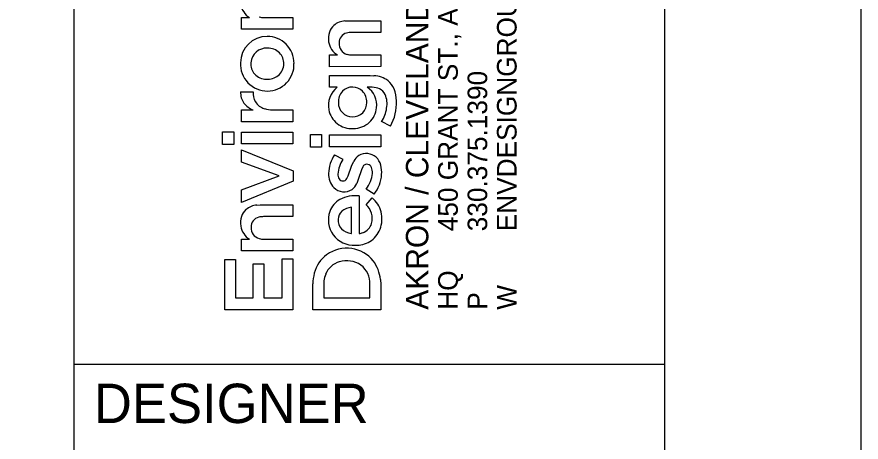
# Model space of a CAD drawing. Extents: x -0.3 to 34, y 0 to 22.
# Drawn here: x 31.854 to 34, y 2.302 to 3.382 of the extents above; entities that cross this region are included whole.
import ezdxf

# ---------------------------------------------------------------- set-up
doc = ezdxf.new("R2010")
doc.units = 0
for name, color, linetype in [('DR_P_Staging_Area', 7, 'Continuous'), ('MT_P_Drums', 7, 'Continuous'), ('SG_P_Poles', 7, 'Continuous')]:
    doc.layers.add(name, color=color, linetype=linetype)

msp = doc.modelspace()

# ---------------------------------------------------------------- linework, layer by layer
at = {"layer": 'DR_P_Staging_Area'}
msp.add_lwpolyline([(0, 0), (34, 0), (34, 22), (0, 22)], close=True, dxfattribs=at)
at = {"layer": 'MT_P_Drums'}
for p, q in [((32, 0.5), (32, 21.5)), ((32, 2.5), (33.5, 2.5))]:
    msp.add_line(p, q, dxfattribs=at)
msp.add_lwpolyline([(1.5, 21.5), (33.5, 21.5), (33.5, 0.5), (1.5, 0.5)], close=True, dxfattribs=at)
at = {"layer": 'SG_P_Poles'}
for p, q in [((32.4254, 3.3509), (32.4254, 3.3807)), ((32.4254, 3.3807), (32.4455, 3.3807)), ((32.4822, 3.3807), (32.5557, 3.3807)), ((32.5557, 3.3807), (32.5557, 3.351)), ((32.6878, 3.3722), (32.6963, 3.3727)), ((32.6963, 3.3727), (32.7792, 3.3727)), ((32.7792, 3.3727), (32.7792, 3.3429)), ((32.5557, 3.351), (32.4254, 3.3509)), ((32.7792, 3.3429), (32.7048, 3.3428)), ((32.6489, 3.2557), (32.6489, 3.2855)), ((32.6489, 3.2855), (32.669, 3.2855)), ((32.7057, 3.2855), (32.7791, 3.2855)), ((32.7791, 3.2855), (32.7792, 3.2558)), ((32.7792, 3.2558), (32.6489, 3.2557)), ((32.6489, 3.2034), (32.6489, 3.2332)), ((32.6489, 3.2332), (32.7524, 3.2332)), ((32.7524, 3.2332), (32.7619, 3.2329)), ((32.6684, 3.2034), (32.6489, 3.2034)), ((32.7576, 3.2036), (32.7449, 3.2036)), ((32.423, 3.1919), (32.4545, 3.1919)), ((32.4254, 3.1159), (32.4254, 3.1458)), ((32.4254, 3.1458), (32.4547, 3.1458)), ((32.5041, 3.1458), (32.5557, 3.1457)), ((32.5557, 3.1457), (32.5556, 3.1159)), ((32.5556, 3.1159), (32.4254, 3.1159)), ((32.8036, 3.1049), (32.7812, 3.116)), ((32.3771, 3.0582), (32.3771, 3.0903)), ((32.3771, 3.0903), (32.4054, 3.0903)), ((32.4054, 3.0903), (32.4054, 3.0582)), ((32.4254, 3.0594), (32.4254, 3.0893)), ((32.4254, 3.0893), (32.5557, 3.0893)), ((32.5557, 3.0893), (32.5557, 3.0594)), ((32.6005, 3.0511), (32.6005, 3.0832)), ((32.6005, 3.0832), (32.6289, 3.0832)), ((32.6289, 3.0832), (32.6289, 3.0511)), ((32.6489, 3.0523), (32.6489, 3.0822)), ((32.6489, 3.0822), (32.7792, 3.0822)), ((32.7792, 3.0822), (32.7792, 3.0523)), ((32.4054, 3.0582), (32.3771, 3.0582)), ((32.5557, 3.0594), (32.4254, 3.0594)), ((32.6289, 3.0511), (32.6005, 3.0511)), ((32.7792, 3.0523), (32.6489, 3.0523)), ((32.4254, 3.0133), (32.4254, 3.0446)), ((32.4254, 3.0446), (32.5567, 2.9913)), ((32.6615, 3.0321), (32.6827, 3.0203)), ((32.5212, 2.978), (32.4254, 3.0133)), ((32.7048, 3.0026), (32.7104, 3.0153)), ((32.5567, 2.9913), (32.5567, 2.9644)), ((32.6967, 2.9787), (32.7048, 3.0026)), ((32.7298, 2.9933), (32.7221, 2.9688)), ((32.7334, 3.001), (32.7298, 2.9933)), ((32.4254, 2.9429), (32.5212, 2.978)), ((32.5567, 2.9644), (32.4254, 2.9109)), ((32.693, 2.9712), (32.6967, 2.9787)), ((32.7221, 2.9688), (32.7182, 2.9592)), ((32.4254, 2.9109), (32.4254, 2.9429)), ((32.7621, 2.9314), (32.742, 2.9447)), ((32.7245, 2.9275), (32.7246, 2.8319)), ((32.7423, 2.9046), (32.7577, 2.922)), ((32.4644, 2.904), (32.4729, 2.9044)), ((32.4729, 2.9044), (32.5557, 2.9044)), ((32.5557, 2.9044), (32.5557, 2.8746)), ((32.7049, 2.8318), (32.7049, 2.8983)), ((32.5557, 2.8746), (32.4814, 2.8746)), ((32.4254, 2.7875), (32.4254, 2.8173)), ((32.4254, 2.8173), (32.4455, 2.8173)), ((32.4822, 2.8173), (32.5557, 2.8173)), ((32.5557, 2.8173), (32.5557, 2.7876)), ((32.7036, 2.8317), (32.7049, 2.8318)), ((32.5557, 2.7876), (32.4254, 2.7875)), ((32.383, 2.6379), (32.383, 2.766)), ((32.383, 2.766), (32.4101, 2.766)), ((32.4101, 2.766), (32.4101, 2.6683)), ((32.455, 2.6683), (32.455, 2.7549)), ((32.455, 2.7549), (32.4822, 2.7549)), ((32.4822, 2.7549), (32.4822, 2.6683)), ((32.5286, 2.6683), (32.5286, 2.7672)), ((32.5286, 2.7672), (32.5557, 2.7672)), ((32.5557, 2.7672), (32.5557, 2.6379)), ((32.6064, 2.638), (32.6064, 2.704)), ((32.6347, 2.7118), (32.6341, 2.7023)), ((32.7785, 2.715), (32.7792, 2.7021)), ((32.6341, 2.7023), (32.6341, 2.6684)), ((32.7515, 2.6683), (32.7515, 2.7024)), ((32.7792, 2.7021), (32.7792, 2.638)), ((32.4101, 2.6683), (32.455, 2.6683)), ((32.4822, 2.6683), (32.5286, 2.6683)), ((32.6341, 2.6684), (32.7515, 2.6683)), ((32.5557, 2.6379), (32.383, 2.6379)), ((32.7792, 2.638), (32.6064, 2.638))]:
    msp.add_line(p, q, dxfattribs=at)
for points in [[(32.4254, 3.3509), (32.4254, 3.3807), (32.4455, 3.3807)], [(32.4822, 3.3807), (32.5557, 3.3807), (32.5557, 3.351), (32.4254, 3.3509)], [(32.6878, 3.3722), (32.6963, 3.3727), (32.7792, 3.3727), (32.7792, 3.3429), (32.7048, 3.3428)], [(32.6489, 3.2557), (32.6489, 3.2855), (32.669, 3.2855)], [(32.7057, 3.2855), (32.7791, 3.2855), (32.7792, 3.2558), (32.6489, 3.2557)], [(32.6684, 3.2034), (32.6489, 3.2034), (32.6489, 3.2332), (32.7524, 3.2332), (32.7619, 3.2329)], [(32.7576, 3.2036), (32.7449, 3.2036)], [(32.423, 3.1919), (32.4545, 3.1919)], [(32.4254, 3.1159), (32.4254, 3.1458), (32.4547, 3.1458)], [(32.5041, 3.1458), (32.5557, 3.1457), (32.5556, 3.1159), (32.4254, 3.1159)], [(32.8036, 3.1049), (32.7812, 3.116)], [(32.6615, 3.0321), (32.6827, 3.0203)], [(32.693, 2.9712), (32.6967, 2.9787), (32.7048, 3.0026), (32.7104, 3.0153)], [(32.7334, 3.001), (32.7298, 2.9933), (32.7221, 2.9688), (32.7182, 2.9592)], [(32.7621, 2.9314), (32.742, 2.9447)], [(32.7245, 2.9275), (32.7246, 2.8319)], [(32.7423, 2.9046), (32.7577, 2.922)], [(32.4644, 2.904), (32.4729, 2.9044), (32.5557, 2.9044), (32.5557, 2.8746), (32.4814, 2.8746)], [(32.7036, 2.8317), (32.7049, 2.8318), (32.7049, 2.8983)], [(32.4254, 2.7875), (32.4254, 2.8173), (32.4455, 2.8173)], [(32.4822, 2.8173), (32.5557, 2.8173), (32.5557, 2.7876), (32.4254, 2.7875)], [(32.7785, 2.715), (32.7792, 2.7021), (32.7792, 2.638), (32.6064, 2.638)], [(32.6064, 2.638), (32.6064, 2.704)], [(32.6347, 2.7118), (32.6341, 2.7023), (32.6341, 2.6684), (32.7515, 2.6683), (32.7515, 2.7024)]]:
    msp.add_lwpolyline(points, dxfattribs=at)
for points in [[(32.3771, 3.0582), (32.3771, 3.0903), (32.4054, 3.0903), (32.4054, 3.0582)], [(32.4254, 3.0594), (32.4254, 3.0893), (32.5557, 3.0893), (32.5557, 3.0594)], [(32.6005, 3.0511), (32.6005, 3.0832), (32.6289, 3.0832), (32.6289, 3.0511)], [(32.6489, 3.0523), (32.6489, 3.0822), (32.7792, 3.0822), (32.7792, 3.0523)], [(32.4254, 2.9109), (32.4254, 2.9429), (32.5212, 2.978), (32.4254, 3.0133), (32.4254, 3.0446), (32.5567, 2.9913), (32.5567, 2.9644)], [(32.383, 2.6379), (32.383, 2.766), (32.4101, 2.766), (32.4101, 2.6683), (32.455, 2.6683), (32.455, 2.7549), (32.4822, 2.7549), (32.4822, 2.6683), (32.5286, 2.6683), (32.5286, 2.7672), (32.5557, 2.7672), (32.5557, 2.6379)]]:
    msp.add_lwpolyline(points, close=True, dxfattribs=at)
for centre, radius, start, end in [((32.4703, 3.4214), 0.0476, 188.9646, 238.6987), ((32.4703, 3.4214), 0.0476, 188.9646, 238.6987), ((32.4818, 3.4229), 0.0421, 254.0891, 270.5284), ((32.4818, 3.4229), 0.0421, 254.0891, 270.5284), ((32.6922, 3.3225), 0.0499, 94.9706, 130.2248), ((32.6922, 3.3225), 0.0499, 94.9706, 130.2248), ((32.6869, 3.3309), 0.0402, 132.2238, 161.6823), ((32.6869, 3.3309), 0.0402, 132.2238, 161.6823), ((32.4901, 3.2654), 0.0674, 89.8476, 179.6405), ((32.4901, 3.2654), 0.0674, 89.8476, 179.6405), ((32.4906, 3.2647), 0.0681, 359.5401, 90.2114), ((32.4906, 3.2647), 0.0681, 359.5401, 90.2114), ((32.7022, 3.3264), 0.056, 162.274, 187.7917), ((32.7022, 3.3264), 0.056, 162.274, 187.7917), ((32.6983, 3.3169), 0.025, 103.6868, 182.214), ((32.6983, 3.3169), 0.025, 103.6868, 182.214), ((32.7045, 3.2968), 0.046, 89.6051, 105.3303), ((32.7045, 3.2968), 0.046, 89.6051, 105.3303), ((32.6937, 3.3262), 0.0476, 188.9646, 238.6987), ((32.6937, 3.3262), 0.0476, 188.9646, 238.6987), ((32.7008, 3.3138), 0.0276, 175.5844, 255.1382), ((32.7008, 3.3138), 0.0276, 175.5844, 255.1382), ((32.4892, 3.2626), 0.0404, 87.0481, 175.5726), ((32.4892, 3.2626), 0.0404, 87.0481, 175.5726), ((32.492, 3.26), 0.043, 45.8426, 90.9801), ((32.492, 3.26), 0.043, 45.8426, 90.9801), ((32.4946, 3.2642), 0.0382, 357.8857, 44.159), ((32.4946, 3.2642), 0.0382, 357.8857, 44.159), ((32.7053, 3.3277), 0.0421, 254.0891, 270.5284), ((32.7053, 3.3277), 0.0421, 254.0891, 270.5284), ((32.4908, 3.2621), 0.0682, 176.8344, 270.4038), ((32.4908, 3.2621), 0.0682, 176.8344, 270.4038), ((32.4873, 3.2625), 0.0385, 175.1538, 221.1471), ((32.4873, 3.2625), 0.0385, 175.1538, 221.1471), ((32.4912, 3.2614), 0.0675, 270.0624, 2.3776), ((32.4912, 3.2614), 0.0675, 270.0624, 2.3776), ((32.4945, 3.2632), 0.0383, 308.2894, 359.4347), ((32.4945, 3.2632), 0.0383, 308.2894, 359.4347), ((32.4892, 3.2661), 0.0423, 223.0999, 268.8089), ((32.4892, 3.2661), 0.0423, 223.0999, 268.8089), ((32.491, 3.2679), 0.0442, 266.5651, 308.0608), ((32.491, 3.2679), 0.0442, 266.5651, 308.0608), ((32.7591, 3.1679), 0.065, 53.4034, 87.4906), ((32.7591, 3.1679), 0.065, 53.4034, 87.4906), ((32.7652, 3.1804), 0.0514, 21.6075, 50.5577), ((32.7652, 3.1804), 0.0514, 21.6075, 50.5577), ((32.7029, 3.1581), 0.0569, 127.3748, 192.2247), ((32.7029, 3.1581), 0.0569, 127.3748, 192.2247), ((32.7069, 3.1693), 0.0346, 88.473, 136.4256), ((32.7069, 3.1693), 0.0346, 88.473, 136.4256), ((32.7081, 3.1696), 0.0342, 44.2719, 90.4762), ((32.7081, 3.1696), 0.0342, 44.2719, 90.4762), ((32.7142, 3.1583), 0.0547, 352.1125, 55.923), ((32.7142, 3.1583), 0.0547, 352.1125, 55.923), ((32.7567, 3.1572), 0.0463, 65.0169, 88.8011), ((32.7567, 3.1572), 0.0463, 65.0169, 88.8011), ((32.7626, 3.1716), 0.0309, 26.2681, 63.803), ((32.7626, 3.1716), 0.0309, 26.2681, 63.803), ((32.7307, 3.1671), 0.0884, 1.1514, 21.3627), ((32.7307, 3.1671), 0.0884, 1.1514, 21.3627), ((32.4662, 3.1888), 0.0433, 175.8731, 216.3475), ((32.4662, 3.1888), 0.0433, 175.8731, 216.3475), ((32.5009, 3.1895), 0.0464, 176.9688, 209.6064), ((32.5009, 3.1895), 0.0464, 176.9688, 209.6064), ((32.7114, 3.166), 0.0401, 137.4674, 182.3324), ((32.7114, 3.166), 0.0401, 137.4674, 182.3324), ((32.7037, 3.166), 0.04, 358.5714, 43.5376), ((32.7037, 3.166), 0.04, 358.5714, 43.5376), ((32.7357, 3.1615), 0.0595, 349.3073, 23.4307), ((32.7357, 3.1615), 0.0595, 349.3073, 23.4307), ((32.4747, 3.1972), 0.0551, 218.0981, 248.7907), ((32.4747, 3.1972), 0.0551, 218.0981, 248.7907), ((32.4951, 3.1881), 0.0408, 211.9447, 253.2028), ((32.4951, 3.1881), 0.0408, 211.9447, 253.2028), ((32.7065, 3.1637), 0.0351, 178.8821, 271.0837), ((32.7065, 3.1637), 0.0351, 178.8821, 271.0837), ((32.7082, 3.164), 0.0355, 268.2788, 1.5502), ((32.7082, 3.164), 0.0355, 268.2788, 1.5502), ((32.7054, 3.1624), 0.1138, 329.6388, 3.26), ((32.7054, 3.1624), 0.1138, 329.6388, 3.26), ((32.5047, 3.2165), 0.0707, 252.4655, 269.573), ((32.5047, 3.2165), 0.0707, 252.4655, 269.573), ((32.7046, 3.157), 0.0584, 190.7518, 231.2892), ((32.7046, 3.157), 0.0584, 190.7518, 231.2892), ((32.7099, 3.1571), 0.0589, 313.742, 353.8554), ((32.7099, 3.1571), 0.0589, 313.742, 353.8554), ((32.7074, 3.1633), 0.0877, 327.3149, 351.5748), ((32.7074, 3.1633), 0.0877, 327.3149, 351.5748), ((32.7063, 3.1611), 0.0627, 232.4606, 272.5902), ((32.7063, 3.1611), 0.0627, 232.4606, 272.5902), ((32.7095, 3.159), 0.0605, 269.6361, 312.7088), ((32.7095, 3.159), 0.0605, 269.6361, 312.7088), ((32.7364, 2.9826), 0.0897, 146.531, 178.7571), ((32.7364, 2.9826), 0.0897, 146.531, 178.7571), ((32.7466, 2.9971), 0.0405, 125.5118, 153.4159), ((32.7466, 2.9971), 0.0405, 125.5118, 153.4159), ((32.7406, 3.0026), 0.0326, 80.1719, 122.5197), ((32.7406, 3.0026), 0.0326, 80.1719, 122.5197), ((32.7428, 2.9982), 0.0367, 47.7934, 84.6892), ((32.7428, 2.9982), 0.0367, 47.7934, 84.6892), ((32.7379, 2.9946), 0.0427, 14.9966, 46.2063), ((32.7379, 2.9946), 0.0427, 14.9966, 46.2063), ((32.7452, 2.9789), 0.0749, 146.5112, 176.9101), ((32.7452, 2.9789), 0.0749, 146.5112, 176.9101), ((32.7438, 2.9963), 0.0114, 76.6609, 155.7053), ((32.7438, 2.9963), 0.0114, 76.6609, 155.7053), ((32.744, 2.9951), 0.0126, 21.5098, 78.5262), ((32.744, 2.9951), 0.0126, 21.5098, 78.5262), ((32.7104, 2.9867), 0.0712, 355.8306, 15.3914), ((32.7104, 2.9867), 0.0712, 355.8306, 15.3914), ((32.6967, 2.9824), 0.0501, 177.5366, 222.7932), ((32.6967, 2.9824), 0.0501, 177.5366, 222.7932), ((32.6931, 2.9823), 0.0228, 178.4747, 211.0868), ((32.6931, 2.9823), 0.0228, 178.4747, 211.0868), ((32.6825, 2.9915), 0.0757, 321.811, 354.7969), ((32.6825, 2.9915), 0.0757, 321.811, 354.7969), ((32.7259, 2.9877), 0.0321, 354.5726, 22.068), ((32.7259, 2.9877), 0.0321, 354.5726, 22.068), ((32.6833, 2.9767), 0.0115, 212.2368, 268.3777), ((32.6833, 2.9767), 0.0115, 212.2368, 268.3777), ((32.6834, 2.9759), 0.0107, 267.716, 333.7337), ((32.6834, 2.9759), 0.0107, 267.716, 333.7337), ((32.6895, 2.9882), 0.0922, 321.9777, 355.8738), ((32.6895, 2.9882), 0.0922, 321.9777, 355.8738), ((32.686, 2.9753), 0.0375, 225.9854, 302.4797), ((32.686, 2.9753), 0.0375, 225.9854, 302.4797), ((32.681, 2.9758), 0.0408, 308.0877, 335.9874), ((32.681, 2.9758), 0.0408, 308.0877, 335.9874), ((32.7152, 2.8441), 0.0838, 83.615, 118.2876), ((32.7152, 2.8441), 0.0838, 83.615, 118.2876), ((32.7174, 2.8717), 0.0644, 13.5336, 51.3615), ((32.7174, 2.8717), 0.0644, 13.5336, 51.3615), ((32.4687, 2.8543), 0.0499, 94.9696, 130.2225), ((32.4687, 2.8543), 0.0499, 94.9696, 130.2225), ((32.7024, 2.8691), 0.0558, 118.8308, 160.6244), ((32.7024, 2.8691), 0.0558, 118.8308, 160.6244), ((32.7079, 2.8561), 0.0424, 94.008, 130.8817), ((32.7079, 2.8561), 0.0424, 94.008, 130.8817), ((32.7038, 2.8656), 0.0549, 19.0357, 45.4406), ((32.7038, 2.8656), 0.0549, 19.0357, 45.4406), ((32.4787, 2.8582), 0.056, 162.2736, 187.7919), ((32.4787, 2.8582), 0.056, 162.2736, 187.7919), ((32.4635, 2.8626), 0.0402, 132.2219, 161.6818), ((32.4635, 2.8626), 0.0402, 132.2219, 161.6818), ((32.7104, 2.8661), 0.0644, 160.5201, 215.7831), ((32.7104, 2.8661), 0.0644, 160.5201, 215.7831), ((32.7005, 2.8663), 0.0298, 132.9851, 177.179), ((32.7005, 2.8663), 0.0298, 132.9851, 177.179), ((32.7107, 2.8697), 0.047, 344.6059, 17.007), ((32.7107, 2.8697), 0.047, 344.6059, 17.007), ((32.7064, 2.8692), 0.0758, 339.3542, 13.3785), ((32.7064, 2.8692), 0.0758, 339.3542, 13.3785), ((32.4748, 2.8487), 0.025, 103.6865, 182.2187), ((32.4748, 2.8487), 0.025, 103.6865, 182.2187), ((32.4811, 2.8286), 0.046, 89.6049, 105.3284), ((32.4811, 2.8286), 0.046, 89.6049, 105.3284), ((32.7017, 2.865), 0.0311, 175.0013, 223.283), ((32.7017, 2.865), 0.0311, 175.0013, 223.283), ((32.7224, 2.8671), 0.035, 288.0077, 343.5508), ((32.7224, 2.8671), 0.035, 288.0077, 343.5508), ((32.4703, 2.858), 0.0476, 188.962, 238.7037), ((32.4703, 2.858), 0.0476, 188.962, 238.7037), ((32.4773, 2.8456), 0.0276, 175.5854, 255.1439), ((32.4773, 2.8456), 0.0276, 175.5854, 255.1439), ((32.7089, 2.8736), 0.0423, 225.0619, 262.7974), ((32.7089, 2.8736), 0.0423, 225.0619, 262.7974), ((32.7247, 2.8522), 0.0202, 269.7003, 294.8711), ((32.7247, 2.8522), 0.0202, 269.7003, 294.8711), ((32.7189, 2.8652), 0.0626, 300.9427, 338.7323), ((32.7189, 2.8652), 0.0626, 300.9427, 338.7323), ((32.4818, 2.8595), 0.0422, 254.0916, 270.5284), ((32.4818, 2.8595), 0.0422, 254.0916, 270.5284), ((32.7125, 2.8705), 0.0687, 217.7452, 271.6543), ((32.7125, 2.8705), 0.0687, 217.7452, 271.6543), ((32.7155, 2.8724), 0.0706, 269.2048, 300.3341), ((32.7155, 2.8724), 0.0706, 269.2048, 300.3341), ((32.6923, 2.7079), 0.0864, 81.194, 125.9984), ((32.6923, 2.7079), 0.0864, 81.194, 125.9984), ((32.6946, 2.7113), 0.0827, 37.8521, 82.402), ((32.6946, 2.7113), 0.0827, 37.8521, 82.402), ((32.6939, 2.7089), 0.0865, 127.2362, 165.148), ((32.6939, 2.7089), 0.0865, 127.2362, 165.148), ((32.6889, 2.7078), 0.054, 106.1881, 157.3861), ((32.6889, 2.7078), 0.054, 106.1881, 157.3861), ((32.6928, 2.6986), 0.0639, 55.6727, 107.2093), ((32.6928, 2.6986), 0.0639, 55.6727, 107.2093), ((32.6929, 2.705), 0.0587, 357.4662, 52.2665), ((32.6929, 2.705), 0.0587, 357.4662, 52.2665), ((32.6859, 2.7057), 0.0931, 5.7333, 37.304), ((32.6859, 2.7057), 0.0931, 5.7333, 37.304), ((32.7143, 2.7028), 0.1078, 164.7861, 179.3704), ((32.7143, 2.7028), 0.1078, 164.7861, 179.3704), ((32.6983, 2.7039), 0.0641, 157.3571, 172.9275), ((32.6983, 2.7039), 0.0641, 157.3571, 172.9275)]:
    msp.add_arc(centre, radius, start, end, dxfattribs=at)

# ---------------------------------------------------------------- texts
for s, height, p in [('450 GRANT ST., AKRON, OH  44311', 0.049846, (32.9749, 2.8374)), ('AKRON / CLEVELAND / COLUMBUS', 0.056969, (32.9001, 2.638)), ('ENVDESIGNGROUP.COM', 0.049846, (33.1244, 2.8374)), ('330.375.1390', 0.049846, (33.0497, 2.8374)), ('HQ ', 0.04985, (32.9749, 2.638)), ('W', 0.0498, (33.1244, 2.638)), ('P', 0.0498, (33.0497, 2.638))]:
    msp.add_text(s, height=height, rotation=90, dxfattribs=at).set_placement(p)
msp.add_text('DESIGNER', height=0.1, dxfattribs=at).set_placement((32.05, 2.35))

doc.saveas('drawing.dxf')
